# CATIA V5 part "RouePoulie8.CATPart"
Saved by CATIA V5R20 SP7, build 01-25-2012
Part number: RouePoulie8
Bounding box of the stored display mesh (mm): x -5 to 35, y -31.997 to 31.997, z 36.028 to 99.972
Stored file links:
  J:\ACHTUNG2\RouePoulie8.CATPart
  J:\ACHTUNG2\cmilovidof.CATProduct
  J:\ACHTUNG\IAO non optimisé fini et qui marche à rendre\Patin2.CATPart
  J:\ACHTUNG\IAO non optimisé fini et qui marche à rendre\Socle.CATPart
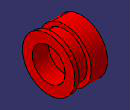
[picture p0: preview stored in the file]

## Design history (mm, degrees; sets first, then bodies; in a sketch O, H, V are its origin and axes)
External parameters (linked from other documents)
  External.diam_roue = 64 mm
Set1
  Line1 "Axe_SocleRoue8": linked copy from another document
Body1 (main body)
  Sketch1 on zx-plane, origin (0, 0, 0), H (-1, 0, 0), V (0, 0, 1)
    line L1 (5, 73) -> (5, 100)
    line L2 (5, 100) -> (-15, 100)
    line L3 (-15, 100) -> (-15, 95)
    line L4 (-15, 95) -> (-30, 95)
    line L5 (-30, 95) -> (-30, 100)
    point P6 (-30, 100)
    line L6 (-30, 100) -> (-35, 100)
    construction line L7 (-35, 100) -> (-35, 73)
    construction line L8 (-35, 73) -> (5, 73)
    line L9 (-35, 100) -> (-35, 88)
    line L10 (-35, 88) -> (-15, 88)
    point P10 (-15, 88)
    line L11 (-15, 88) -> (-15, 73)
    point P11 (-15, 73)
    line L12 (5, 73) -> (-15, 73)
    reference projected line E1 (0, 68) -> (-20, 68) from Line1
    reference projected line E2 (0, 68) -> (-20, 68) from Line1
    length L8 = 40 {= 40mm}
    distance L4 L6 = 5 {= 5mm}
    distance L5 L7 = 5 {= 5mm}
    distance L3 L5 = 15 {= 15*External.diam_roue /64}
    distance L10 L6 = 12 {= 12mm}
    distance E1 L2 = 32 {= 32*External.diam_roue /64}
    distance E2 L12 = 5 {= 5*External.diam_roue /64}
    distance L9 V = 35
    vertical: L1 V, L3 V, L5 V, L7 V, L9 V, L11 V
    horizontal: L2 H, L4 H, L6 H, L8 H, L10 H, L12 H
    coincidence: P6 L2, P10 L3, P11 L8
  Shaft1: profile Sketch1, axis Line1, angle 360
